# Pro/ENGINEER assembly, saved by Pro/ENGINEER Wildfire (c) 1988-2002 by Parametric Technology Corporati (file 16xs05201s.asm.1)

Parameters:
  NB = "16XS05201S"
  NN = "16 - Series"
  NT = "Medium Heavy Duty Caster"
